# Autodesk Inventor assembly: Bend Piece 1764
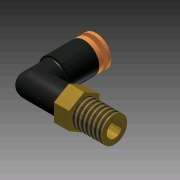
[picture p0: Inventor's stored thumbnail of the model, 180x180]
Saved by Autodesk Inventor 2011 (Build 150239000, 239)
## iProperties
Created: 2010-02
Part Number: Bend Piece 1764
Document SubType Name: Assembly
Designer: jgehrig
Author: jgehrig
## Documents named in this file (4)
- R:\CAD Archives\Pnewmatics\Pnematics Bend Piece\Bend Piece 1764.iam
- R:\CAD Archives\Pnewmatics\Pnematics Bend Piece\Pnematic Screw Part 1764.ipt
- R:\CAD Archives\Pnewmatics\pnewmatic screw\Pnewmatic Screw Part 2 1764.ipt
- R:\CAD Archives\Pnewmatics\Pnematics Bend Piece\Bend Piece 1764.ipt
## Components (3 placed, 3 different names)
1. Bend Piece 1764:1 — Insert:1, Insert:2
2. Pnematic Screw Part 1764:1 — Insert:2
3. Pnewmatic Screw Part 2 1764:1 — Insert:1
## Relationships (2: Insert 2)
- Insert:1: Bend Piece 1764:1 ↔ Pnewmatic Screw Part 2 1764:1
- Insert:2: Bend Piece 1764:1 ↔ Pnematic Screw Part 1764:1
